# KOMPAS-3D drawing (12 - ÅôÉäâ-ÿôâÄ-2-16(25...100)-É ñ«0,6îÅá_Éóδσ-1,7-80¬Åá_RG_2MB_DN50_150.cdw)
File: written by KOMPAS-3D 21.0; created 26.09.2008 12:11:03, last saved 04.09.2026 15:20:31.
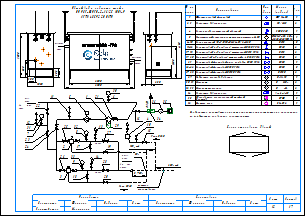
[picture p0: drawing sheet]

Sheets 1-2: A3, landscape

Document properties: Наименование: Макро:21; Автор: RaskoAdmin; Форматы листов документа: 2xA3; Полное имя файла: \\ur38nt01\Departments\КТО\КБ ПУРДГ\Заявки\Прайс-лист на типовые шкафы ГРПШ\ПУРДГ_стандарт_30_04_2026\ПУРДГ с RG_2MB\ПУРДГ-ШУГО-2-16(25...100)-Р до0,6МПа_Рвых-1,7-80кПа_RG_2MB_DN50_150.cdw

Title block, sheet 1: Наименование: Пункт учета газа / ПУГ-Ш-400-Р / ЛГТИ.485922.001ТУ; designation: ЛГТИ.03.4411141; sheet number: 1; Количество листов документа: 2; organisation: ООО "ЭЛЬСТЕР Газэлектроника"; Форматы листов документа: A3; stored path: C:\Рабочие документы\Компас\ПУГ\Схема.cdw; Разработал: Устинов; Проверил: Кошкин; Утвердил: Кошкин
Title block, sheet 2: sheet number: 2; stored path: D:\Рабочие документы\Заявки\ПУРДГ\ПУРДГ-ШУЭО-2-100-Р 4411220.cdw; designation, second copy: ЛГТИ.03.4411141-

Views: Вид 1, Вид 2
Referenced files: wcvoit.frw
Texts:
  Normal
  DN150
  Выход газа
  DN50
  Вход газа
  logo-rasko-ge.png
  DN 1
  местное
  сопротивление
  Римп DN20
  Выход
  газа
  Р=     кПа
  Вход
  Р=       МПа
  PDI
  Общий вид и габариты шкафа
  ПУРДГ-ШУГО-2-16(25...100)-Р
  № на
  схеме
  Усл.
  обозн.
  Марка
  (модель)
  Кол.
  Фильтр газовый фланцевый
  ФГ 16-50
  Регулятор давления газа
  RG/2MB
  Клапан предохранительный сбросной
  КПС DN20
  Измерительный комплекс с ротационным счетчиком Ду50
  СГ-ЭК-Р-(0,2...2,0)-
  Кран кнопочный VE-РАСКО-НЗ-1,6-G1/2-М20
  DN15
  Кран шаровой "под приварку" штуцерный DN20 PN16
  DN20
  Кран шаровой "под приварку" штуцерный DN15 PN16
  Кран шаровой "под приварку" штуцерный п/п DN20 PN16
  Кран шаровой фланцевый с мех. приводом DN50 PN16
  Кран шаровой фланцевый DN50 PN16
  Кран шаровой фланцевый DN150 PN16
  Индикатор перепада давления
  Манометр
  Манометр-напоромер
  Обогреватель газогорелочный шкафной
  (Эльтон")
  Счетчик газа
  Delta 15
  0...     МПа
  0...     кПа
  Venio-A-15
  ОГШН
  BK-G1,6
  Схема открывания дверей
  Предприятие изготовитель может заменять комплектующие на аналогичные,
  не ухудшающие заявленных характеристик.
  Должность
  Конструктор
  Фамилия
  Подпись
  Дата
  Согласовано
  Максимкин
  Лист
  Листов
  POLYLINE_STYLE_0.18_RGB_0_0_0
  POLYLINE_STYLE_0.50_RGB_0_0_0
  POLYLINE_STYLE_0.34_RGB_0_0_0
  PHANTOM_RGB_0_0_0_SC_1_THICK_0.18
  K5LT_THIN_RGB_0_0_0_THICK_0.18
  K5LT32769_RGB_0_0_0_THICK_0.18
  K5LT12_RGB_0_0_0_SC_1_THICK_0.18
  K5LT_DASHED_RGB_0_0_0_SC_1_THICK_0.18
  ACISOTGL_RGB_0_0_0_SC_0.8_THICK_0.25
  CONTINUOUS_RGB_0_127_31_THICK_0.3
  CONTINUOUS_RGB_0_0_255_THICK_0.35
  CONTINUOUS_RGB_255_0_0_THICK_0.35
  POLYLINE_STYLE_0.25_RGB_0_0_0
  CONTINUOUS_RGB_0_0_0_THICK_0.5
  POLYLINE_STYLE_0.35_RGB_0_0_255
  CONTINUOUS_RGB_0_0_0_THICK_0.4
  CONTINUOUS_RGB_0_0_0_THICK_0.35
  НЕВИДИМАЯ_RGB_0_0_0_SC_0.3_THICK_0.25
  СONTINUOUS_RGB_0_0_0_THICK_0.25
  ОСЕВАЯ2_RGB_248_153_30_SC_0.3_THICK_0.25
  Без оформления
Dimensions and other numbers on the sheet: 1; 1500; 250; 300; 1050; 550; 305; 2500; 4130; 2000; 2800; 5,,,7DN 1; 7; 31; 12; 22; 23; 24; 11; 5; 21; 6; 30; 25; 32; 8; 2; 17; 13; 27; 19; 4; 10; 15; 26; 33; 9; 3; 18; 14; 28; 20; 29; 2, 3; 6-10; 11-16; 17, 18; 19, 20; 22-26; 27, 28; 30, 31; 32, 33; 34; 35; 36; 16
